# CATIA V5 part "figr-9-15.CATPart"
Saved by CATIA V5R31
Part number: Part1
Bounding box of the stored display mesh (mm): x -77.304 to 77.304, y -77.304 to 118.168, z 0 to 125
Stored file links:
  D:\PROJECTS\Project 2021\US EDITION\CATIA V5 6R 2021\Resources\Part Files\c09_catia_v5_6r2021_prt\c09_catia_v5_6r2021_prt\figr-9-15.CATPart
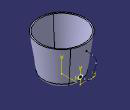
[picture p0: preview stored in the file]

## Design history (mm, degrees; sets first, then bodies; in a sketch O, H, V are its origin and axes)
Set1
  Plane1: type Normal, Curve Sketch3, RefPoint vertex of Sketch3
Body1 (main body)
  Sketch1 on yz-plane, origin (0, 0, 0), H (0, 1, 0), V (0, 0, 1)
    line L1 (0, 0) -> (60, 0)
    point P1 (60, 0)
    point P2 (60, 0)
    line L2 (60, 0) -> (77.5, 125)
    point P3 (77.5, 125)
    line L3 (77.5, 125) -> (0, 125)
    point P4 (0, 125)
    line L4 (0, 125) -> (0, 0)
    axis line L5 (0, 150.2858) -> (0, -31.0593)
    point P5 (0, 150.2858)
    radius about axis P1 L5 = 60
    radius about axis P3 L5 = 77.5
    distance L3 L1 = 125
    horizontal: L1 H, L3 H
    coincidence: P4 V, P2 P1, P5 V
    vertical: L4 V, L5 V
  Shaft1: profile Sketch1, axis Sketch1.L5, angle 360
  Fillet1: radius 15, on edge [face of Shaft1 | face of Shaft1]
  Shell1: ExtOffset 0, Face face of Shaft1, IntOffset 4
  Sketch2 on Plane1, origin (0, 62.9841, 0), H (-1, 0, 0), V (0, 0, 1)
    circle A1 centre (0, 22.002) radius 7.5
    reference projected point E1 (0, 22.002) from vertex of Sketch3
    radius A1 = 7.5
    concentricity: A1 E1
  Sketch3 on yz-plane, origin (0, 0, 0), H (0, 1, 0), V (0, 0, 1)
    line L1 (62.9841, 22.002) -> (78.2172, 22.002)
    arc A1 centre (78.2172, 44.1133) radius 22.1113 from (78.2172, 22.002) to (97.9307, 34.0988) ccw
    arc A2 centre (-112.3295, 140.9107) radius 235.8349 from (97.9307, 34.0988) to (117.8681, 89.6549) ccw
    arc A3 centre (104.0328, 92.7355) radius 14.1742 from (117.8681, 89.6549) to (104.4272, 106.9041) ccw
    arc A4 centre (93.6744, -279.4123) radius 386.4661 from (104.4272, 106.9041) to (82.9216, 106.9041) ccw
    horizontal: L1 H
    tangency: A1 L1, A2 A1, A3 A2, A4 A3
